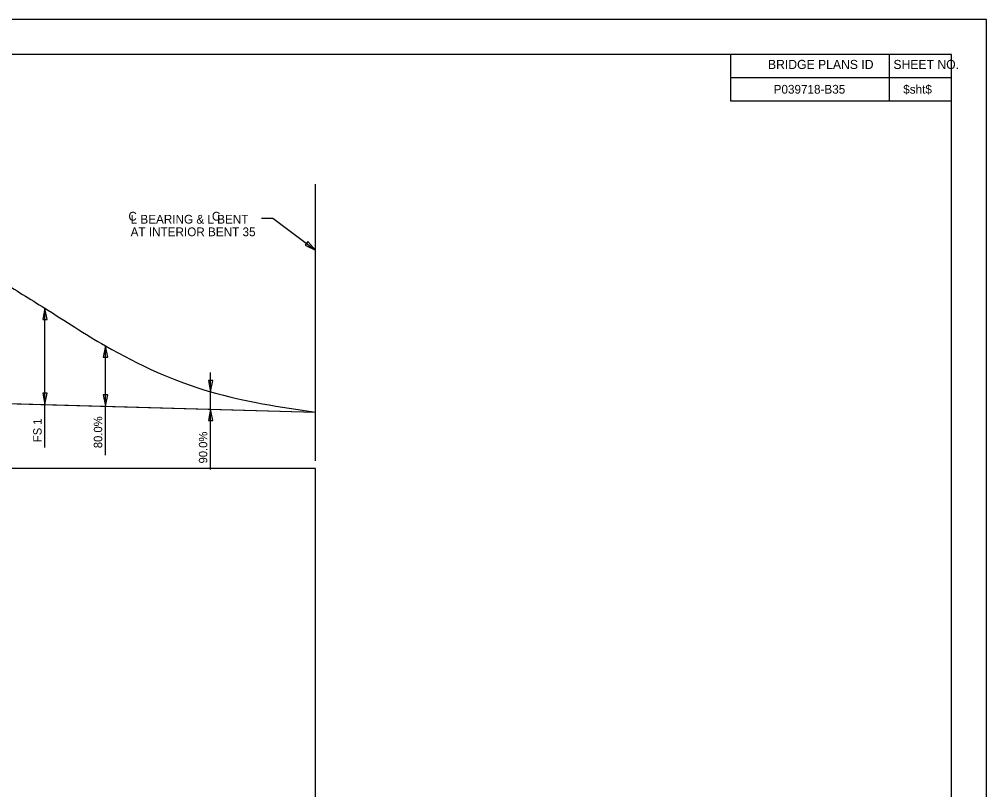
# Model space of a CAD drawing. Extents: x -133.1 to -97, y -1.7 to 20.3.
# Drawn here: x -110.95 to -97.14, y 9.31 to 20.31 of the extents above; entities that cross this region are included whole.
import ezdxf

# ---------------------------------------------------------------- set-up
doc = ezdxf.new("R2010")
doc.units = 0
for name, color, linetype in [('BR_AUTO DIMENSION', 7, 'Continuous'), ('BR_BORDER LINES', 7, 'Continuous'), ('BR_CENTER LINES', 7, 'Continuous'), ('BR_TABLE LINES', 7, 'Continuous'), ('BR_TEXT', 7, 'Continuous'), ('Default', 7, 'Continuous'), ('Level 31', 7, 'Continuous')]:
    doc.layers.add(name, color=color, linetype=linetype)

msp = doc.modelspace()

# ---------------------------------------------------------------- linework, layer by layer
at = {"layer": 'BR_AUTO DIMENSION'}
for p, q in [((-107.493, 17.471), (-107.333, 17.471)), ((-107.333, 17.471), (-106.721, 17.012))]:
    msp.add_line(p, q, dxfattribs=at)
for points in [[(-106.869, 17.086), (-106.721, 17.012), (-106.831, 17.136)], [(-110.555, 16.022), (-110.587, 16.184), (-110.618, 16.022)], [(-109.689, 15.484), (-109.721, 15.646), (-109.752, 15.484)], [(-108.252, 15.153), (-108.221, 14.991), (-108.189, 15.153)], [(-110.618, 14.97), (-110.587, 14.807), (-110.555, 14.97)], [(-109.752, 14.946), (-109.721, 14.783), (-109.689, 14.946)], [(-108.189, 14.579), (-108.221, 14.741), (-108.252, 14.579)], [(-124.721, 1.92), (-106.721, 1.92), (-106.721, 13.893), (-124.721, 13.893)]]:
    msp.add_lwpolyline(points, close=True, dxfattribs=at)
at = {"layer": 'BR_BORDER LINES'}
for p, q in [((-97.642, 19.809), (-131.308, 19.809)), ((-100.794, 19.142), (-100.794, 19.809)), ((-98.528, 19.142), (-98.528, 19.809)), ((-97.642, -1.191), (-97.642, 19.809)), ((-100.794, 19.479), (-97.642, 19.479)), ((-98.528, 19.479), (-97.642, 19.479)), ((-97.642, 19.142), (-100.794, 19.142))]:
    msp.add_line(p, q, dxfattribs=at)
at = {"layer": 'BR_CENTER LINES'}
msp.add_line((-106.721, 14.003), (-106.721, 17.956), dxfattribs=at)
at = {"layer": 'BR_TABLE LINES'}
for p, q in [((-110.587, 14.196), (-110.587, 16.184)), ((-109.721, 14.087), (-109.721, 15.646)), ((-108.221, 13.882), (-108.221, 15.266)), ((-121.721, 15.118), (-106.721, 14.699))]:
    msp.add_line(p, q, dxfattribs=at)
msp.add_spline([(-121.721, 15.118), (-120.221, 16.504), (-118.721, 17.637), (-117.221, 18.348), (-115.721, 18.551), (-114.221, 18.248), (-112.721, 17.531), (-111.221, 16.578), (-110.587, 16.184), (-109.721, 15.646), (-108.221, 14.991), (-106.721, 14.7)], degree=3, dxfattribs=at)
at = {"layer": 'Default'}
msp.add_lwpolyline([(-121.721, 15.118), (-106.721, 14.699), (-106.721, 14.699)], dxfattribs=at)
at = {"layer": 'Level 31'}
msp.add_lwpolyline([(-133.141, -1.691), (-97.141, -1.691), (-97.141, 20.309), (-133.141, 20.309)], close=True, dxfattribs=at)

# ---------------------------------------------------------------- texts
at = {"layer": 'BR_AUTO DIMENSION'}
for s, p in [('C', (-109.394, 17.435)), ('C', (-108.202, 17.435)), ('L BEARING & L BENT', (-109.362, 17.392)), ('AT INTERIOR BENT 35', (-109.362, 17.212))]:
    msp.add_text(s, height=0.125, dxfattribs=at).set_placement(p)
at = {"layer": 'BR_TEXT'}
for s, height, p in [('BRIDGE PLANS ID', 0.13, (-100.263, 19.6)), ('SHEET NO.', 0.13, (-98.472, 19.6)), ('P039718-B35', 0.125, (-100.182, 19.248)), ('$sht$', 0.125, (-98.332, 19.248))]:
    msp.add_text(s, height=height, dxfattribs=at).set_placement(p)
for s, p in [('FS 1', (-110.633, 14.271)), ('80.0%', (-109.768, 14.185)), ('90.0%', (-108.268, 13.967))]:
    msp.add_text(s, height=0.12, rotation=90, dxfattribs=at).set_placement(p)

doc.saveas('drawing.dxf')
